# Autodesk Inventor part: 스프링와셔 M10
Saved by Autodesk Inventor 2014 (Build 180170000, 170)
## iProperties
Created: 2026-03
Part Number: 스프링와셔 M10
Material: 강철, 연강
Document SubType Name: Modeling
Designer: dg
Density: 7.86 g/cm^3
Appearance: 강철
Mass: 3.10189 g
Surface Area: 5.48825 cm^2
Volume: 0.394643 cm^3
Author: jhkim
Description: 스프링 잠금 와셔
Creation Date: 2025-06-27
Sending System: Autodesk Inventor 2026
Preprocessor: ST-DEVELOPER v20.1
Author: dg
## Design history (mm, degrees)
node "스프링와셔 M101"
body "Solid1"
node "기준1"
